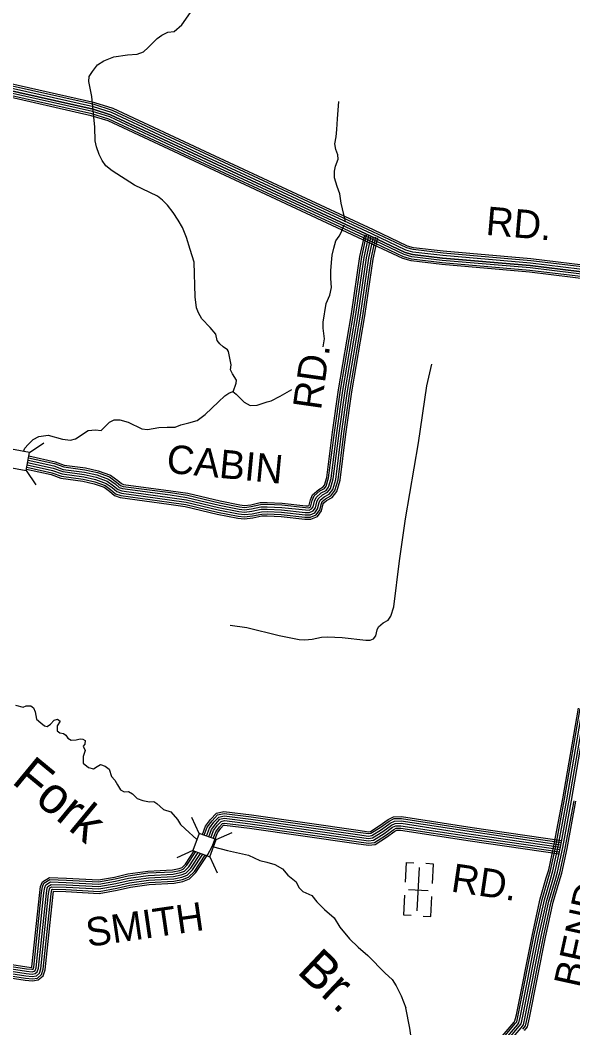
# Model space of a CAD drawing. Extents: x 1788175 to 1969470, y 584502 to 738744.
# Drawn here: x 1844183 to 1851363, y 700327 to 713422 of the extents above; entities that cross this region are included whole.
import ezdxf

# ---------------------------------------------------------------- set-up
doc = ezdxf.new("R2010")
doc.units = 0
for name, color, linetype in [('DESIGN - DRAINAGE - Bridges and Cross Drains Size Text', 7, 'Continuous'), ('DESIGN - ROW - Right-of-Way and Easement Labels', 7, 'Continuous'), ('DESIGN - TRANSPORTATION - Text', 7, 'Continuous'), ('DESIGN - UTILITIES - Cable (Underground) with Text', 7, 'Continuous'), ('SURVEY - CONTOURS - Index with Text', 7, 'Continuous'), ('SURVEY - DRAINAGE - Storm Sewer', 7, 'Continuous'), ('SURVEY - TRANSPORTATION - Roads', 7, 'Continuous')]:
    doc.layers.add(name, color=color, linetype=linetype)

msp = doc.modelspace()

# ---------------------------------------------------------------- linework, layer by layer
at = {"layer": 'DESIGN - TRANSPORTATION - Text'}
for points in [[(1846952, 708593), (1846987, 708706), (1846993, 708746), (1846940, 708824), (1846917, 708879), (1846926, 708944), (1846888, 709115), (1846878, 709138), (1846819, 709179), (1846777, 709215), (1846740, 709258), (1846723, 709341), (1846650, 709427), (1846541, 709541), (1846498, 709617), (1846473, 709683), (1846455, 709827), (1846442, 710277), (1846392, 710441), (1846344, 710598), (1846290, 710726), (1846237, 710821), (1846171, 710922), (1846098, 711017), (1846033, 711085), (1845967, 711136), (1845667, 711276), (1845376, 711466), (1845295, 711531), (1845246, 711599), (1845209, 711678), (1845174, 711774), (1845157, 711856), (1845151, 712030), (1845112, 712432), (1845086, 712562), (1845074, 712624), (1845081, 712690), (1845122, 712755), (1845189, 712840), (1845268, 712895), (1845400, 712945), (1845578, 712971), (1845702, 712979), (1845785, 713012), (1845845, 713067), (1845963, 713185), (1846023, 713229), (1846099, 713264), (1846183, 713276), (1846282, 713363), (1846457, 713610)], [(1848285, 711742), (1848272, 711814), (1848289, 711906), (1848298, 712002), (1848306, 712139), (1848322, 712367)], [(1848403, 710801), (1848403, 710822), (1848352, 711046), (1848336, 711164), (1848301, 711259), (1848268, 711375), (1848265, 711461), (1848280, 711523), (1848315, 711614), (1848310, 711670), (1848285, 711742)], [(1848121, 709178), (1848138, 709281), (1848119, 709418), (1848119, 709497), (1848158, 709742), (1848207, 709850), (1848227, 709948), (1848217, 710065), (1848217, 710163), (1848227, 710271), (1848236, 710369), (1848256, 710457), (1848285, 710555), (1848325, 710614), (1848354, 710663), (1848393, 710761)], [(1844224, 707819), (1844245, 707860), (1844287, 707907), (1844351, 707973), (1844425, 708012), (1844547, 708027), (1844733, 707978), (1844836, 707963), (1844902, 707983), (1845067, 708091), (1845161, 708097), (1845233, 708088), (1845281, 708138), (1845344, 708199), (1845404, 708230), (1845478, 708229), (1845584, 708197), (1845764, 708113), (1845838, 708104), (1845986, 708130), (1846094, 708133), (1846196, 708133), (1846269, 708164), (1846373, 708191), (1846481, 708219), (1846588, 708298), (1846760, 708463), (1846841, 708542), (1846893, 708575), (1846947, 708597), (1846989, 708562), (1847094, 708457), (1847171, 708416), (1847261, 708417), (1847391, 708461), (1847443, 708475), (1847560, 708536)], [(1847560, 708536), (1847714, 708622)], [(1844124, 704520), (1844220, 704496), (1844262, 704514), (1844320, 704513), (1844356, 704488), (1844379, 704436), (1844396, 704340), (1844451, 704289), (1844500, 704254), (1844534, 704245), (1844579, 704275), (1844626, 704326), (1844668, 704338), (1844703, 704311), (1844665, 704252), (1844662, 704189), (1844697, 704163), (1844745, 704154), (1844777, 704130), (1844800, 704093), (1844844, 704065), (1844912, 704070), (1844964, 704085), (1844998, 704080), (1845028, 704062), (1845023, 704014), (1845003, 703988), (1845026, 703932), (1845003, 703854), (1845001, 703766), (1845070, 703709), (1845134, 703692), (1845185, 703725), (1845227, 703751), (1845285, 703730), (1845338, 703691), (1845371, 703594), (1845412, 703546), (1845447, 703487)], [(1845447, 703487), (1845488, 703420), (1845536, 703395), (1845590, 703397), (1845643, 703368), (1845704, 703309), (1845776, 703280), (1845864, 703266), (1845920, 703270), (1845958, 703241), (1846046, 703166), (1846138, 703136), (1846225, 703033), (1846265, 702971), (1846328, 702913), (1846476, 702773)], [(1846695, 702679), (1846876, 702632), (1847148, 702571), (1847297, 702502), (1847387, 702479), (1847492, 702451), (1847591, 702394), (1847662, 702311), (1847769, 702223), (1847804, 702152), (1847857, 702099), (1847972, 702048), (1848035, 701965), (1848136, 701865), (1848262, 701759), (1848334, 701636), (1848460, 701482), (1848574, 701374), (1848699, 701268), (1848925, 701040), (1849014, 700957), (1849067, 700874), (1849133, 700745), (1849192, 700586)], [(1849173, 697556), (1849155, 697744), (1849153, 697902), (1849172, 698082), (1849178, 698352), (1849202, 698526), (1849202, 698616), (1849145, 698703), (1849108, 698784), (1849108, 698932), (1849116, 699052), (1849124, 699172), (1849139, 699242), (1849182, 699335), (1849210, 699429), (1849204, 699543), (1849187, 699636), (1849199, 699756), (1849229, 699875), (1849241, 700009), (1849269, 700141), (1849245, 700322), (1849192, 700586)]]:
    msp.add_lwpolyline(points, dxfattribs=at)
at = {"layer": 'DESIGN - UTILITIES - Cable (Underground) with Text'}
for p, q in [((1849197, 702478), (1849184, 702220)), ((1849197, 702478), (1849297, 702473)), ((1849553, 702456), (1849455, 702461)), ((1849540, 702205), (1849553, 702456)), ((1849176, 702052), (1849163, 701796)), ((1849229, 702124), (1849483, 702111)), ((1849518, 701774), (1849532, 702034)), ((1849163, 701796), (1849262, 701791)), ((1849419, 701779), (1849518, 701774))]:
    msp.add_line(p, q, dxfattribs=at)
msp.add_lwpolyline([(1849341, 701850), (1849370, 702413)], dxfattribs=at)
at = {"layer": 'SURVEY - CONTOURS - Index with Text'}
for points in [[(1851668, 710218), (1850819, 710320), (1849678, 710419), (1849294, 710465), (1849214, 710487), (1848774, 710696), (1846649, 711686), (1845390, 712275), (1845152, 712349), (1843928, 712625), (1842146, 712926), (1841312, 713044), (1840981, 713061), (1840497, 713050), (1840098, 713053), (1839938, 713095), (1839682, 713179), (1839542, 713203), (1839379, 713217), (1838414, 713349), (1837866, 713448)], [(1851665, 710193), (1850817, 710295), (1849676, 710393), (1849289, 710440), (1849206, 710463), (1848763, 710673), (1846639, 711662), (1845381, 712250), (1845145, 712324), (1843923, 712600), (1842142, 712900), (1841309, 713018), (1840980, 713035), (1840497, 713024), (1840095, 713028), (1839931, 713070), (1839676, 713154), (1839539, 713177), (1839376, 713192), (1838410, 713323), (1837904, 713415)], [(1851649, 710070), (1850804, 710171), (1849663, 710270), (1849266, 710318), (1849162, 710346), (1848710, 710561), (1846586, 711550), (1845336, 712135), (1845113, 712204), (1843899, 712479), (1842123, 712778), (1841298, 712895), (1840979, 712911), (1840498, 712900), (1840079, 712904), (1839896, 712951), (1839646, 713034), (1839523, 713054), (1839362, 713068), (1838391, 713201), (1837881, 713293)], [(1851653, 710100), (1850807, 710202), (1849666, 710301), (1849272, 710348), (1849173, 710375), (1848724, 710589), (1846599, 711578), (1845347, 712164), (1845121, 712234), (1843905, 712509), (1842127, 712808), (1841301, 712926), (1840979, 712942), (1840497, 712931), (1840083, 712935), (1839905, 712981), (1839653, 713064), (1839527, 713085), (1839366, 713099), (1838396, 713231), (1837887, 713324)], [(1837892, 713354), (1838400, 713262), (1839369, 713130), (1839531, 713116), (1839661, 713094), (1839914, 713010), (1840087, 712966), (1840497, 712962), (1840980, 712973), (1841304, 712957), (1842132, 712839), (1843911, 712539), (1845129, 712264), (1845358, 712193), (1846612, 711606), (1848737, 710617), (1849184, 710404), (1849278, 710379), (1849669, 710331), (1850810, 710233), (1851657, 710131)], [(1851657, 710131), (1850810, 710233), (1849669, 710331), (1849278, 710379), (1849184, 710404), (1848737, 710617), (1846612, 711606), (1845358, 712193), (1845129, 712264), (1843911, 712539), (1842132, 712839), (1841304, 712957), (1840980, 712973), (1840497, 712962), (1840087, 712966), (1839914, 713010), (1839661, 713094), (1839531, 713116), (1839369, 713130), (1838400, 713262), (1837892, 713354)], [(1851661, 710162), (1850813, 710264), (1849672, 710362), (1849284, 710409), (1849195, 710433), (1848750, 710645), (1846626, 711634), (1845370, 712222), (1845137, 712294), (1843917, 712570), (1842137, 712869), (1841306, 712988), (1840980, 713004), (1840497, 712993), (1840091, 712997), (1839922, 713040), (1839668, 713124), (1839535, 713147), (1839372, 713161), (1838405, 713293), (1837898, 713385)], [(1851646, 710045), (1850801, 710147), (1849660, 710245), (1849261, 710294), (1849154, 710323), (1848700, 710538), (1846576, 711528), (1845327, 712112), (1845107, 712180), (1843894, 712454), (1842119, 712753), (1841295, 712870), (1840978, 712886), (1840498, 712875), (1840076, 712879), (1839889, 712927), (1839640, 713010), (1839520, 713030), (1839359, 713044), (1838387, 713176), (1837877, 713269)], [(1850420, 700191), (1850599, 700402), (1850611, 700418), (1850630, 700496), (1850837, 701540), (1850939, 702002), (1851018, 702275), (1851049, 702379), (1851117, 702693), (1851231, 703302), (1851435, 704482)], [(1850440, 700176), (1850618, 700387), (1850634, 700407), (1850654, 700491), (1850861, 701535), (1850963, 701996), (1851042, 702268), (1851073, 702373), (1851141, 702688), (1851256, 703298), (1851459, 704478)], [(1850465, 700157), (1850642, 700367), (1850662, 700393), (1850684, 700484), (1850892, 701528), (1850993, 701989), (1851071, 702259), (1851103, 702366), (1851171, 702682), (1851286, 703292), (1851490, 704474)], [(1850489, 700138), (1850666, 700348), (1850691, 700380), (1850714, 700477), (1850922, 701522), (1851023, 701981), (1851101, 702250), (1851133, 702358), (1851202, 702675), (1851317, 703287), (1851521, 704469)], [(1850514, 700119), (1850691, 700328), (1850720, 700366), (1850745, 700471), (1850952, 701515), (1851053, 701973), (1851131, 702242), (1851163, 702350), (1851232, 702669), (1851347, 703281), (1851551, 704465)], [(1850715, 700309), (1850748, 700352), (1850775, 700464), (1850983, 701509), (1851083, 701966), (1851161, 702233), (1851193, 702343), (1851262, 702663), (1851378, 703276)], [(1850735, 700293), (1850772, 700341), (1850800, 700459), (1851008, 701504), (1851108, 701959), (1851185, 702226), (1851218, 702336), (1851288, 702658), (1851403, 703271)]]:
    msp.add_lwpolyline(points, dxfattribs=at)
at = {"layer": 'SURVEY - DRAINAGE - Storm Sewer'}
for p, q in [((1844304, 707804), (1844492, 707931)), ((1844259, 707570), (1844387, 707382)), ((1846507, 702855), (1846412, 703062)), ((1846729, 702773), (1846936, 702867)), ((1846424, 702633), (1846218, 702538)), ((1846647, 702550), (1846741, 702343))]:
    msp.add_line(p, q, dxfattribs=at)
for points in [[(1844026, 707615), (1844259, 707570), (1844304, 707804), (1844070, 707848)], [(1846507, 702855), (1846424, 702633), (1846647, 702550), (1846729, 702773)]]:
    msp.add_lwpolyline(points, close=True, dxfattribs=at)
at = {"layer": 'SURVEY - TRANSPORTATION - Roads'}
for points in [[(1846114, 707134), (1846328, 707104), (1846742, 707004), (1847011, 706949), (1847099, 706941), (1847207, 706953), (1847324, 706979), (1847391, 706981), (1847572, 706973), (1847881, 706938), (1847960, 706937), (1848046, 706973), (1848099, 707047), (1848120, 707135), (1848126, 707149), (1848163, 707181), (1848235, 707220), (1848295, 707297), (1848338, 707444), (1848413, 708044), (1848491, 708591), (1848660, 709578), (1848767, 710317), (1848830, 710594)], [(1846118, 707160), (1846333, 707129), (1846748, 707029), (1847015, 706975), (1847099, 706967), (1847203, 706979), (1847321, 707004), (1847391, 707007), (1847574, 706999), (1847883, 706964), (1847955, 706963), (1848029, 706994), (1848075, 707058), (1848096, 707143), (1848105, 707165), (1848148, 707202), (1848218, 707240), (1848272, 707309), (1848312, 707449), (1848388, 708047), (1848466, 708595), (1848635, 709582), (1848742, 710322), (1848804, 710600)], [(1846122, 707190), (1846338, 707159), (1846754, 707060), (1847020, 707005), (1847099, 706998), (1847198, 707009), (1847317, 707035), (1847391, 707038), (1847577, 707029), (1847885, 706995), (1847949, 706994), (1848009, 707019), (1848046, 707071), (1848066, 707152), (1848079, 707183), (1848130, 707228), (1848197, 707264), (1848244, 707323), (1848282, 707455), (1848357, 708051), (1848435, 708600), (1848604, 709587), (1848711, 710328), (1848774, 710607)], [(1846127, 707221), (1846344, 707190), (1846761, 707090), (1847024, 707036), (1847098, 707029), (1847192, 707040), (1847313, 707066), (1847391, 707069), (1847579, 707060), (1847887, 707026), (1847943, 707025), (1847989, 707045), (1848018, 707084), (1848037, 707162), (1848053, 707202), (1848112, 707253), (1848177, 707288), (1848216, 707338), (1848251, 707461), (1848326, 708055), (1848405, 708605), (1848573, 709592), (1848681, 710333), (1848744, 710613)], [(1846127, 707221), (1846344, 707190), (1846761, 707090), (1847024, 707036), (1847098, 707029), (1847192, 707040), (1847313, 707066), (1847391, 707069), (1847579, 707060), (1847887, 707026), (1847943, 707025), (1847989, 707045), (1848018, 707084), (1848037, 707162), (1848053, 707202), (1848112, 707253), (1848177, 707288), (1848216, 707338), (1848251, 707461), (1848326, 708055), (1848405, 708605), (1848573, 709592), (1848681, 710333), (1848744, 710613)], [(1846131, 707252), (1846350, 707220), (1846768, 707120), (1847029, 707067), (1847098, 707060), (1847187, 707070), (1847309, 707097), (1847391, 707100), (1847581, 707091), (1847889, 707057), (1847937, 707056), (1847969, 707070), (1847989, 707097), (1848007, 707172), (1848028, 707220), (1848094, 707279), (1848156, 707312), (1848187, 707352), (1848221, 707468), (1848296, 708059), (1848374, 708610), (1848543, 709597), (1848650, 710339), (1848714, 710620)], [(1846135, 707282), (1846356, 707251), (1846774, 707150), (1847033, 707098), (1847098, 707091), (1847182, 707101), (1847305, 707128), (1847391, 707131), (1847584, 707122), (1847891, 707088), (1847931, 707087), (1847949, 707095), (1847960, 707111), (1847978, 707182), (1848002, 707239), (1848077, 707304), (1848136, 707337), (1848159, 707367), (1848190, 707474), (1848265, 708063), (1848343, 708614), (1848512, 709601), (1848620, 710345), (1848683, 710627)], [(1846139, 707307), (1846361, 707275), (1846780, 707175), (1847037, 707122), (1847097, 707116), (1847178, 707125), (1847302, 707152), (1847391, 707156), (1847586, 707147), (1847892, 707113), (1847926, 707112), (1847933, 707115), (1847937, 707121), (1847954, 707189), (1847981, 707254), (1848062, 707325), (1848120, 707356), (1848137, 707378), (1848166, 707479), (1848240, 708067), (1848319, 708618), (1848488, 709605), (1848595, 710349), (1848659, 710633)], [(1846911, 705559), (1847129, 705528), (1847546, 705428), (1847809, 705375), (1847883, 705368), (1847977, 705378), (1848098, 705405), (1848176, 705407), (1848364, 705399), (1848672, 705364), (1848728, 705364), (1848774, 705383), (1848802, 705423), (1848822, 705501), (1848838, 705540), (1848897, 705592), (1848962, 705627), (1849000, 705676), (1849036, 705800), (1849111, 706394), (1849189, 706943), (1849358, 707930), (1849465, 708672), (1849529, 708952)], [(1844274, 707645), (1844603, 707571), (1844727, 707525), (1845009, 707487), (1845161, 707453), (1845301, 707403), (1845377, 707347), (1845438, 707295), (1845498, 707274), (1846122, 707190)], [(1844279, 707675), (1844611, 707601), (1844735, 707555), (1845014, 707517), (1845170, 707483), (1845315, 707431), (1845396, 707371), (1845454, 707323), (1845505, 707304), (1846127, 707221)], [(1844279, 707675), (1844611, 707601), (1844735, 707555), (1845014, 707517), (1845170, 707483), (1845315, 707431), (1845396, 707371), (1845454, 707323), (1845505, 707304), (1846127, 707221)], [(1844285, 707706), (1844620, 707631), (1844742, 707585), (1845020, 707548), (1845179, 707513), (1845330, 707458), (1845416, 707396), (1845470, 707350), (1845513, 707334), (1846131, 707252)], [(1844291, 707736), (1844629, 707660), (1844750, 707616), (1845025, 707578), (1845187, 707543), (1845345, 707486), (1845435, 707420), (1845485, 707377), (1845520, 707364), (1846135, 707282)], [(1844296, 707761), (1844636, 707684), (1844756, 707640), (1845030, 707603), (1845194, 707566), (1845356, 707508), (1845450, 707440), (1845498, 707399), (1845526, 707389), (1846138, 707307)], [(1844263, 707589), (1844586, 707517), (1844713, 707469), (1844999, 707431), (1845146, 707398), (1845274, 707352), (1845342, 707303), (1845409, 707246), (1845484, 707218), (1846115, 707134)], [(1844268, 707614), (1844594, 707541), (1844720, 707495), (1845003, 707456), (1845153, 707423), (1845286, 707375), (1845358, 707323), (1845422, 707268), (1845491, 707243), (1846118, 707160)], [(1846551, 702839), (1846592, 702948), (1846657, 703035), (1846733, 703117), (1846830, 703139), (1847186, 703095), (1848572, 702895), (1848708, 702876), (1848732, 702879), (1848847, 702952), (1848962, 703035), (1849035, 703071), (1849137, 703072), (1850056, 702932), (1851214, 702761)], [(1846574, 702830), (1846613, 702936), (1846676, 703019), (1846746, 703094), (1846831, 703114), (1847182, 703070), (1848569, 702870), (1848708, 702851), (1848740, 702856), (1848860, 702932), (1848975, 703014), (1849040, 703046), (1849135, 703047), (1850053, 702907), (1851211, 702737)], [(1846603, 702820), (1846641, 702921), (1846700, 702999), (1846762, 703066), (1846833, 703083), (1847178, 703039), (1848564, 702839), (1848708, 702820), (1848751, 702826), (1848878, 702906), (1848991, 702987), (1849048, 703015), (1849133, 703016), (1850048, 702877), (1851206, 702706)], [(1842847, 701164), (1844248, 700946), (1844343, 700937), (1844417, 700951), (1844481, 701004), (1844506, 701083), (1844610, 702065), (1844616, 702103), (1844777, 702098), (1845210, 702075), (1845445, 702116), (1845614, 702155), (1845857, 702191), (1846184, 702206), (1846298, 702230), (1846382, 702262), (1846467, 702345), (1846621, 702581), (1846679, 702685), (1846746, 702863), (1846791, 702923), (1846825, 702959), (1846839, 702962), (1847162, 702922), (1848548, 702722), (1848708, 702700), (1848793, 702712), (1848944, 702807), (1849052, 702885), (1849075, 702897), (1849125, 702897), (1850030, 702759), (1851189, 702589)], [(1846632, 702809), (1846668, 702906), (1846723, 702979), (1846778, 703038), (1846835, 703051), (1847174, 703009), (1848560, 702809), (1848708, 702789), (1848762, 702796), (1848895, 702880), (1849007, 702961), (1849055, 702984), (1849131, 702985), (1850043, 702846), (1851202, 702676)], [(1846632, 702809), (1846668, 702906), (1846723, 702979), (1846778, 703038), (1846835, 703051), (1847174, 703009), (1848560, 702809), (1848708, 702789), (1848762, 702796), (1848895, 702880), (1849007, 702961), (1849055, 702984), (1849131, 702985), (1850043, 702846), (1851202, 702676)], [(1846661, 702798), (1846696, 702890), (1846747, 702959), (1846795, 703010), (1846836, 703020), (1847170, 702978), (1848556, 702778), (1848708, 702757), (1848773, 702766), (1848913, 702854), (1849022, 702934), (1849062, 702953), (1849129, 702954), (1850039, 702815), (1851197, 702645)], [(1846690, 702787), (1846723, 702875), (1846771, 702939), (1846811, 702982), (1846838, 702989), (1847166, 702947), (1848551, 702747), (1848708, 702726), (1848784, 702736), (1848930, 702829), (1849038, 702907), (1849069, 702922), (1849127, 702923), (1850034, 702785), (1851193, 702614)], [(1841951, 701339), (1842852, 701190), (1844251, 700971), (1844342, 700963), (1844406, 700975), (1844459, 701019), (1844481, 701088), (1844584, 702068), (1844594, 702125), (1844601, 702129), (1844778, 702123), (1845208, 702101), (1845439, 702141), (1845609, 702181), (1845854, 702216), (1846181, 702232), (1846291, 702255), (1846368, 702284), (1846447, 702361), (1846585, 702573)], [(1841956, 701369), (1842856, 701220), (1844255, 701002), (1844340, 700995), (1844393, 701004), (1844432, 701037), (1844451, 701094), (1844553, 702072), (1844564, 702135), (1844568, 702146), (1844593, 702161), (1844779, 702154), (1845206, 702132), (1845433, 702172), (1845604, 702211), (1845851, 702247), (1846177, 702263), (1846282, 702284), (1846351, 702311), (1846423, 702381), (1846555, 702584)], [(1841962, 701400), (1842861, 701251), (1844259, 701033), (1844339, 701026), (1844379, 701033), (1844405, 701055), (1844420, 701101), (1844523, 702077), (1844534, 702143), (1844542, 702166), (1844584, 702192), (1844780, 702185), (1845204, 702163), (1845427, 702202), (1845598, 702242), (1845848, 702278), (1846173, 702294), (1846273, 702314), (1846334, 702337), (1846399, 702401), (1846525, 702595)], [(1841962, 701400), (1842861, 701251), (1844259, 701033), (1844339, 701026), (1844379, 701033), (1844405, 701055), (1844420, 701101), (1844523, 702077), (1844534, 702143), (1844542, 702166), (1844584, 702192), (1844780, 702185), (1845204, 702163), (1845427, 702202), (1845598, 702242), (1845848, 702278), (1846173, 702294), (1846273, 702314), (1846334, 702337), (1846399, 702401), (1846525, 702595)], [(1841967, 701431), (1842866, 701282), (1844263, 701064), (1844337, 701057), (1844366, 701062), (1844379, 701073), (1844390, 701107), (1844492, 702081), (1844504, 702150), (1844517, 702187), (1844576, 702223), (1844782, 702216), (1845203, 702194), (1845421, 702232), (1845592, 702272), (1845846, 702309), (1846169, 702325), (1846265, 702344), (1846317, 702364), (1846375, 702420), (1846496, 702606)], [(1841972, 701461), (1842871, 701312), (1844267, 701095), (1844336, 701088), (1844352, 701091), (1844359, 701114), (1844461, 702085), (1844473, 702158), (1844491, 702208), (1844568, 702255), (1844783, 702247), (1845201, 702225), (1845415, 702263), (1845586, 702303), (1845843, 702340), (1846165, 702355), (1846256, 702374), (1846300, 702391), (1846350, 702440), (1846466, 702617)], [(1841976, 701486), (1842875, 701337), (1844270, 701119), (1844333, 701113), (1844335, 701119), (1844437, 702088), (1844449, 702164), (1844471, 702225), (1844562, 702279), (1844784, 702272), (1845199, 702250), (1845410, 702287), (1845582, 702327), (1845840, 702365), (1846162, 702380), (1846249, 702398), (1846286, 702412), (1846331, 702456), (1846442, 702626)]]:
    msp.add_lwpolyline(points, dxfattribs=at)

# ---------------------------------------------------------------- texts
at = {"layer": 'DESIGN - DRAINAGE - Bridges and Cross Drains Size Text'}
for s, rotation, p in [('Fork', 320.4521, (1844059, 703517)), ('Br.', 316.6882, (1847765, 701048))]:
    msp.add_text(s, height=475, rotation=rotation, dxfattribs=at).set_placement(p)
at = {"layer": 'DESIGN - ROW - Right-of-Way and Easement Labels'}
for s, rotation, p in [('RD.', 355.0821, (1850223, 710633)), ('RD.', 81.8959, (1848090, 708346)), ('CABIN', 354.5066, (1846074, 707542)), ('RD.', 351.6363, (1849768, 702100)), ('BEND', 77.6044, (1851474, 700832)), ('SMITH', 8.2893, (1845065, 701378))]:
    msp.add_text(s, height=370, rotation=rotation, dxfattribs=at).set_placement(p)

doc.saveas('drawing.dxf')
